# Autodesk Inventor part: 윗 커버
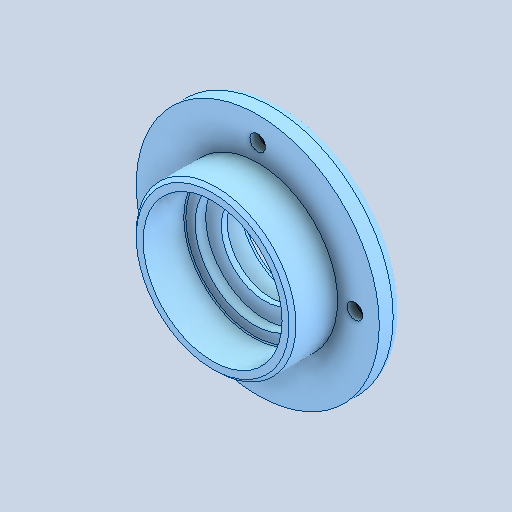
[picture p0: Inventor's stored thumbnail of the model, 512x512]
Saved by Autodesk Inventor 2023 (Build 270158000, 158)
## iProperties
Created: 2025-04
Part Number: 윗 커버
Material: 알루미늄 6061
Document SubType Name: Modeling
Designer: ADMIN_PC
Density: 2.71 g/cm^3
Appearance: 기본값
Company: 한국ATC센터
Author: jhkim
Revision Number: 1
Sending System: Autodesk Inventor 2026
Preprocessor: ST-DEVELOPER v20.1
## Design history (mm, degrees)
feature "솔리드1"
node "솔리드2"
